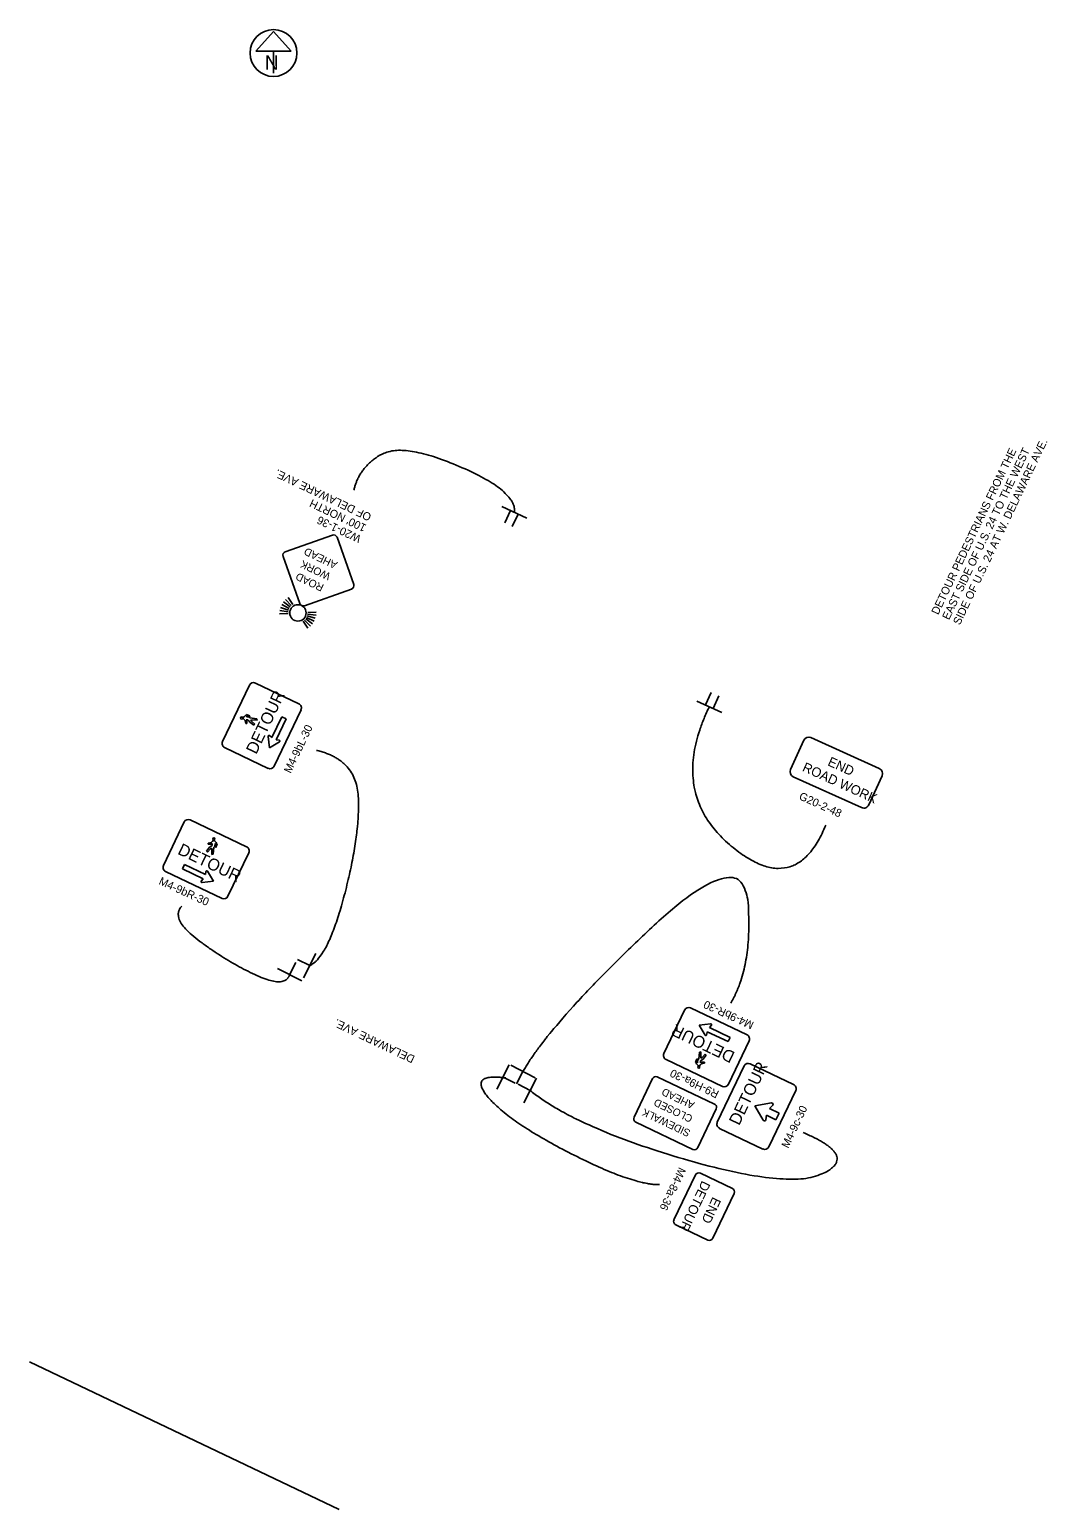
# Model space of a CAD drawing. Extents: x 186402 to 186758, y 352964 to 353482.
import ezdxf

# ---------------------------------------------------------------- set-up
doc = ezdxf.new("R2010")
doc.units = 0
for name, color, linetype in [('SH_Data', 7, 'Continuous'), ('SH_Masking', 7, 'Continuous'), ('SH_Text', 7, 'Continuous'), ('SN_P_Text', 7, 'Continuous')]:
    doc.layers.add(name, color=color, linetype=linetype)

msp = doc.modelspace()

# ---------------------------------------------------------------- linework, layer by layer
at = {"layer": 'SH_Data'}
msp.add_line((186510.16, 352964.46), (186401.84, 353016.1), dxfattribs=at)
msp.add_circle((186487.18, 353473.94), 8.2, dxfattribs=at)
at = {"layer": 'SH_Masking'}
for p, q in [((186487.18, 353481.42), (186481.03, 353474.59)), ((186493.33, 353474.59), (186487.18, 353481.42)), ((186481.03, 353474.59), (186493.33, 353474.59)), ((186487.18, 353474.59), (186487.18, 353466.86)), ((186567.13, 353315.32), (186575.79, 353311.19)), ((186570.16, 353313.88), (186568.1, 353309.54)), ((186571.46, 353313.26), (186571.46, 353313.26)), ((186572.76, 353312.64), (186570.7, 353308.3)), ((186493.02, 353280.18), (186490.68, 353281.97)), ((186493.43, 353280.63), (186491.45, 353282.78)), ((186493.91, 353280.99), (186492.31, 353283.49)), ((186492.31, 353277.9), (186489.32, 353277.76)), ((186492.33, 353278.51), (186489.39, 353278.89)), ((186492.45, 353279.1), (186489.66, 353279.98)), ((186492.69, 353279.67), (186490.07, 353281.02)), ((186501.81, 353276.19), (186499, 353277.05)), ((186502.07, 353277.26), (186499.13, 353277.64)), ((186502.14, 353278.36), (186499.16, 353278.24)), ((186499.23, 353272.7), (186497.6, 353275.22)), ((186500.1, 353273.39), (186498.09, 353275.59)), ((186500.8, 353274.25), (186498.48, 353276.03)), ((186501.37, 353275.19), (186498.77, 353276.53)), ((186477.3, 353240.43), (186477.52, 353239.34)), ((186477.59, 353240.7), (186478.26, 353240.71)), ((186477.84, 353240.36), (186477.59, 353240.7)), ((186477.6, 353241.82), (186477.75, 353242.11)), ((186478.97, 353242.02), (186477.73, 353242.5)), ((186477.73, 353242.5), (186477.73, 353242.49)), ((186477.75, 353242.11), (186478.83, 353241.77)), ((186478.26, 353240.71), (186478.54, 353240.34)), ((186478.83, 353241.77), (186478.97, 353242.02)), ((186478.91, 353241.36), (186478.89, 353241.42)), ((186481.33, 353241.07), (186478.91, 353241.36)), ((186479.48, 353240.21), (186479.25, 353240.66)), ((186479.25, 353240.66), (186481.43, 353240.59)), ((186481.43, 353240.59), (186481.33, 353241.07)), ((186490.11, 353241.74), (186486.63, 353234.45)), ((186488.13, 353233.73), (186491.61, 353241.02)), ((186491.61, 353241.02), (186490.11, 353241.74)), ((186477.52, 353239.34), (186477.83, 353239.39)), ((186477.83, 353239.39), (186477.84, 353240.36)), ((186478.54, 353240.34), (186478.94, 353239.85)), ((186478.94, 353239.85), (186480.29, 353238.8)), ((186480.69, 353239.11), (186479.48, 353240.21)), ((186480.29, 353238.8), (186480.69, 353239.11)), ((186485.33, 353234.89), (186485.84, 353230.85)), ((186485.84, 353230.85), (186489.29, 353233)), ((186486.63, 353234.45), (186485.85, 353235.16)), ((186489.17, 353233.58), (186488.13, 353233.73)), ((186464.84, 353196.09), (186463.79, 353194.74)), ((186463.79, 353194.74), (186464.1, 353194.34)), ((186464.1, 353194.34), (186465.19, 353195.56)), ((186465.42, 353197.73), (186464.33, 353197.51)), ((186464.33, 353197.51), (186464.38, 353197.2)), ((186464.38, 353197.2), (186465.35, 353197.19)), ((186465.33, 353196.5), (186464.84, 353196.09)), ((186465.19, 353195.56), (186465.65, 353195.78)), ((186465.69, 353196.77), (186465.33, 353196.5)), ((186465.35, 353197.19), (186465.68, 353197.44)), ((186465.65, 353195.78), (186465.58, 353193.6)), ((186465.68, 353197.44), (186465.69, 353196.77)), ((186466.06, 353193.7), (186466.35, 353196.12)), ((186466.35, 353196.12), (186466.41, 353196.15)), ((186467.1, 353197.29), (186466.76, 353196.2)), ((186466.76, 353196.2), (186467.01, 353196.06)), ((186466.81, 353197.44), (186467.1, 353197.29)), ((186467.01, 353196.06), (186467.49, 353197.3)), ((186467.49, 353197.3), (186467.48, 353197.3)), ((186455.34, 353188.51), (186456.05, 353190.02)), ((186456.05, 353190.02), (186463.35, 353186.54)), ((186465.58, 353193.6), (186466.06, 353193.7)), ((186462.63, 353185.04), (186455.34, 353188.51)), ((186461.92, 353184.26), (186462.63, 353185.04)), ((186466.23, 353184.24), (186462.19, 353183.74)), ((186463.35, 353186.54), (186463.5, 353187.58)), ((186464.08, 353187.7), (186466.23, 353184.24)), ((186502.06, 353158.97), (186497.68, 353150.43)), ((186497.08, 353149.32), (186488.55, 353153.71)), ((186492.81, 353151.51), (186495.01, 353155.78)), ((186499.87, 353154.7), (186495.6, 353156.89)), ((186636.11, 353133.87), (186640.15, 353134.37)), ((186638.26, 353130.42), (186636.11, 353133.87)), ((186640.42, 353133.85), (186639.71, 353133.08)), ((186639.71, 353133.08), (186647, 353129.6)), ((186638.99, 353131.57), (186638.84, 353130.54)), ((186646.29, 353128.1), (186638.99, 353131.57)), ((186647, 353129.6), (186646.29, 353128.1)), ((186635.33, 353122.05), (186634.85, 353120.82)), ((186635.24, 353120.83), (186635.58, 353121.91)), ((186635.58, 353121.91), (186635.33, 353122.05)), ((186635.99, 353121.99), (186635.93, 353121.97)), ((186636.28, 353124.41), (186635.99, 353121.99)), ((186636.76, 353124.51), (186636.28, 353124.41)), ((186636.64, 353121.34), (186637.01, 353121.62)), ((186636.65, 353120.67), (186636.64, 353121.34)), ((186636.69, 353122.33), (186636.76, 353124.51)), ((186637.15, 353122.56), (186636.69, 353122.33)), ((186637.01, 353121.62), (186637.5, 353122.02)), ((186638.24, 353123.77), (186637.15, 353122.56)), ((186637.5, 353122.02), (186638.55, 353123.37)), ((186638.55, 353123.37), (186638.24, 353123.77)), ((186565.33, 353111.44), (186569.72, 353119.98)), ((186570.2, 353119.82), (186578.74, 353115.44)), ((186574.47, 353117.63), (186572.28, 353113.36)), ((186634.85, 353120.82), (186634.86, 353120.81)), ((186635.53, 353120.68), (186635.24, 353120.83)), ((186636.99, 353120.92), (186636.65, 353120.67)), ((186636.92, 353120.38), (186638.01, 353120.6)), ((186637.96, 353120.91), (186636.99, 353120.92)), ((186638.01, 353120.6), (186637.96, 353120.91)), ((186567.53, 353115.71), (186571.8, 353113.52)), ((186577.02, 353111.01), (186572.76, 353113.21)), ((186579.22, 353115.28), (186574.83, 353106.74)), ((186619.83, 353115.21), (186613.37, 353101.66)), ((186641.51, 353106.23), (186621.41, 353115.82)), ((186661.43, 353106.67), (186655.68, 353105.7)), ((186660.77, 353104.67), (186661.88, 353105.85)), ((186635.67, 353091.02), (186642.11, 353104.54)), ((186655.68, 353105.7), (186658.55, 353100.61)), ((186659.46, 353100.79), (186659.68, 353102.39)), ((186659.68, 353102.39), (186659.7, 353102.38)), ((186659.7, 353102.38), (186663.03, 353100.79)), ((186663.03, 353100.79), (186664.12, 353103.08)), ((186613.97, 353099.96), (186633.97, 353090.42))]:
    msp.add_line(p, q, dxfattribs=at)
for points in [[(186491.32, 353299.44), (186507.82, 353305.29)], [(186509.42, 353304.53), (186515.26, 353288.03)], [(186496.41, 353281.35), (186490.56, 353297.85)], [(186514.5, 353286.44), (186498, 353280.59)], [(186478.76, 353252.8), (186469.35, 353233.06)], [(186496.08, 353246.28), (186480.84, 353253.54)], [(186487.4, 353224.45), (186496.82, 353244.2)], [(186470.09, 353230.98), (186485.32, 353223.71)], [(186455.96, 353204.95), (186448.7, 353189.71)], [(186477.79, 353196.27), (186458.05, 353205.68)], [(186471.27, 353178.96), (186478.53, 353194.19)], [(186449.44, 353187.63), (186469.19, 353178.22)], [(186631.07, 353139.16), (186623.81, 353123.93)], [(186652.9, 353130.48), (186633.15, 353139.9)], [(186646.38, 353113.17), (186653.64, 353128.4)], [(186624.55, 353121.84), (186644.29, 353112.43)], [(186651.88, 353119.58), (186642.5, 353099.9)], [(186669.18, 353113.11), (186654.02, 353120.34)], [(186660.55, 353091.3), (186669.94, 353110.98)], [(186664.12, 353103.08), (186660.79, 353104.66)], [(186643.26, 353097.77), (186658.42, 353090.54)], [(186634.83, 353081.48), (186627.34, 353065.77)], [(186647.76, 353076.75), (186636.57, 353082.09)], [(186640.88, 353059.32), (186648.37, 353075.02)], [(186627.96, 353064.04), (186639.15, 353058.7)]]:
    msp.add_lwpolyline(points, dxfattribs=at)
for centre, radius in [((186487.18, 353473.94), 8.2), ((186495.73, 353278.09), 2.87), ((186476.07, 353241.31), 0.383), ((186466.3, 353198.97), 0.383), ((186636.04, 353119.15), 0.383)]:
    msp.add_circle(centre, radius, dxfattribs=at)
for centre, radius, start, end in [((186508.24, 353304.11), 1.25, 19.5098, 109.5098), ((186491.74, 353298.27), 1.25, 109.5098, 199.5098), ((186514.08, 353287.61), 1.25, 289.5098, 19.5098), ((186497.59, 353281.77), 1.25, 199.5098, 289.5098), ((186480.17, 353252.13), 1.56, 64.5098, 154.5098), ((186495.4, 353244.87), 1.56, 334.5098, 64.5098), ((186485.64, 353234.93), 0.313, 47.5578, 187.1083), ((186470.76, 353232.39), 1.56, 154.5098, 244.5098), ((186489.12, 353233.27), 0.313, 301.9112, 81.4617), ((186485.99, 353225.12), 1.56, 244.5098, 334.5098), ((186457.37, 353204.27), 1.56, 64.5098, 154.5098), ((186477.12, 353194.86), 1.56, 334.5098, 64.5098), ((186450.11, 353189.04), 1.56, 154.5098, 244.5098), ((186462.15, 353184.05), 0.313, 137.5578, 277.1083), ((186463.81, 353187.53), 0.313, 31.9112, 171.4617), ((186469.86, 353179.63), 1.56, 244.5098, 334.5098), ((186632.48, 353138.49), 1.56, 64.5098, 154.5098), ((186640.19, 353134.06), 0.312, 317.5578, 97.1083), ((186638.53, 353130.58), 0.312, 211.9112, 351.4617), ((186652.23, 353129.07), 1.56, 334.5098, 64.5098), ((186625.22, 353123.25), 1.56, 154.5098, 244.5098), ((186653.33, 353118.89), 1.6, 64.5098, 154.5098), ((186620.96, 353114.63), 1.27, 64.5098, 154.5098), ((186644.96, 353113.84), 1.56, 244.5098, 334.5098), ((186668.49, 353111.66), 1.6, 334.5098, 64.5098), ((186640.97, 353105.09), 1.27, 334.5098, 64.5098), ((186661.52, 353106.19), 0.493, 316.872, 99.589), ((186614.52, 353101.11), 1.27, 154.5098, 244.5098), ((186658.98, 353100.85), 0.493, 209.4305, 352.1476), ((186643.95, 353099.22), 1.6, 154.5098, 244.5098), ((186634.52, 353091.57), 1.27, 244.5098, 334.5098), ((186659.11, 353091.99), 1.6, 244.5098, 334.5098), ((186636.01, 353080.92), 1.3, 64.5098, 154.5098), ((186647.2, 353075.58), 1.3, 334.5098, 64.5098), ((186628.52, 353065.21), 1.3, 154.5098, 244.5098), ((186639.71, 353059.88), 1.3, 244.5098, 334.5098)]:
    msp.add_arc(centre, radius, start, end, dxfattribs=at)
for points, degree in [([(186571.46, 353313.26), (186572.64, 353320.51), (186532.28, 353337.95), (186516.98, 353328.76), (186515.31, 353320.97)], 2), ([(186477.73, 353242.49), (186477.41, 353242.21), (186476.89, 353241.78), (186476.7, 353241.62), (186476.65, 353241.56), (186476.62, 353241.49), (186476.55, 353241.33), (186476.64, 353241.04), (186476.89, 353240.78), (186477.06, 353240.58), (186477.3, 353240.43)], 3), ([(186478.89, 353241.42), (186478.84, 353241.49), (186478.76, 353241.58), (186478.55, 353241.66), (186478.37, 353241.7), (186478.04, 353241.76), (186477.81, 353241.8), (186477.6, 353241.82)], 3), ([(186499.87, 353154.7), (186506.11, 353157.37), (186517.41, 353199.58), (186516.41, 353226.78), (186502.19, 353230)], 2), ([(186467.48, 353197.3), (186467.2, 353197.62), (186466.77, 353198.14), (186466.61, 353198.33), (186466.55, 353198.38), (186466.48, 353198.41), (186466.32, 353198.49), (186466.02, 353198.39), (186465.77, 353198.14), (186465.57, 353197.97), (186465.42, 353197.73)], 3), ([(186466.41, 353196.15), (186466.48, 353196.19), (186466.57, 353196.27), (186466.65, 353196.48), (186466.69, 353196.66), (186466.75, 353196.99), (186466.79, 353197.22), (186466.81, 353197.44)], 3), ([(186647.19, 353141.6), (186654.8, 353154.34), (186651.77, 353198.57), (186584.16, 353134.54), (186574.47, 353117.63)], 2), ([(186492.81, 353151.51), (186491.35, 353146.54), (186470.25, 353156.44), (186450.96, 353171.17), (186455.12, 353175.53)], 2), ([(186635.93, 353121.97), (186635.86, 353121.92), (186635.77, 353121.84), (186635.69, 353121.63), (186635.65, 353121.45), (186635.59, 353121.13), (186635.55, 353120.9), (186635.53, 353120.68)], 3), ([(186634.86, 353120.81), (186635.14, 353120.49), (186635.57, 353119.97), (186635.73, 353119.78), (186635.79, 353119.73), (186635.86, 353119.7), (186636.02, 353119.63), (186636.31, 353119.72), (186636.57, 353119.97), (186636.77, 353120.14), (186636.92, 353120.38)], 3), ([(186568.49, 353115.4), (186555.07, 353117.17), (186569.7, 353099.93), (186613.01, 353077.87), (186622.31, 353078.08)], 2), ([(186577.02, 353111.01), (186592.96, 353098.08), (186668.25, 353076.07), (186691.7, 353088.25), (186672.58, 353096.26)], 2)]:
    msp.add_open_spline(points, degree=degree, dxfattribs=at)
at = {"layer": 'SH_Text'}
for p, q in [((186644.09, 353243.3), (186635.34, 353247.26)), ((186638.4, 353245.87), (186640.39, 353250.24)), ((186641.03, 353244.68), (186643.01, 353249.06)), ((186639.72, 353245.28), (186639.72, 353245.28)), ((186639.72, 353245.28), (186639.72, 353245.28))]:
    msp.add_line(p, q, dxfattribs=at)
for points in [[(186672.8, 353233.52), (186668.16, 353223.28)], [(186699.19, 353223.62), (186675.28, 353234.46)], [(186669.09, 353220.79), (186693, 353209.96)], [(186695.48, 353210.89), (186700.13, 353221.14)]]:
    msp.add_lwpolyline(points, dxfattribs=at)
for centre, radius, start, end in [((186674.51, 353232.75), 1.87, 65.6179, 155.6179), ((186669.87, 353222.5), 1.88, 155.6179, 245.6179), ((186698.42, 353221.91), 1.88, 335.6179, 65.6179), ((186693.78, 353211.67), 1.87, 245.6179, 335.6179)]:
    msp.add_arc(centre, radius, start, end, dxfattribs=at)
at = {"layer": 'SN_P_Text'}
msp.add_open_spline([(186680.44, 353203.82), (186669.75, 353177.82), (186625.03, 353215.2), (186639.72, 353245.28)], degree=2, dxfattribs=at)

# ---------------------------------------------------------------- texts
at = {"layer": 'SH_Masking'}
msp.add_text('N', height=5, dxfattribs=at).set_placement((186484.16, 353468.12))
for s, height, rotation, p in [('DETOUR PEDESTRIANS FROM THE', 2.8, 64.5098, (186719.78, 353277.22)), ('EAST SIDE OF U.S. 24 TO THE WEST ', 2.8, 64.5098, (186723.57, 353275.42)), ('SIDE OF U.S. 24 AT W. DELAWARE AVE.', 2.8, 64.5098, (186727.36, 353273.61)), ('OF DELAWARE AVE.', 2.8, 154.5098, (186521.73, 353312.57)), ("100' NORTH", 2.8, 154.5098, (186519.93, 353308.78)), ('W20-1-36', 2.8, 154.5098, (186518.12, 353304.99)), ('AHEAD', 2.665, 154.5098, (186509.78, 353295.76)), ('WORK', 2.665, 154.5098, (186507.42, 353291.81)), ('ROAD', 2.665, 154.5098, (186505.05, 353287.86)), ('DETOUR', 4.167, 64.5098, (186481.15, 353228.38)), ('M4-9bL-30', 2.8, 64.5098, (186493.2, 353221.75)), ('DETOUR', 4.167, 334.5098, (186453.37, 353193.88)), ('M4-9bR-30', 2.8, 335.4956, (186446.8, 353183.26)), ('M4-9bR-30', 2.8, 155.4956, (186655.53, 353134.85)), ('DELAWARE AVE.', 2.8, 154.5098, (186536.89, 353122.97)), ('DETOUR', 4.167, 154.5098, (186648.97, 353124.23)), ('R9-H9a-30', 2.8, 154.5098, (186643.35, 353110.71)), ('DETOUR', 4.167, 64.5098, (186650.15, 353098.53)), ('AHEAD', 2.627, 154.5098, (186634.78, 353106.76)), ('CLOSED', 2.627, 154.5098, (186634.14, 353102.05)), ('SIDEWALK', 2.627, 154.5098, (186633.35, 353097.03)), ('M4-9c-30', 2.8, 64.5098, (186667.31, 353090.6)), ('M4-8a-36', 2.8, 244.5098, (186629.12, 353084.37)), ('DETOUR', 3.333, 244.5098, (186637.2, 353079.68)), ('END', 3.333, 244.5098, (186640.93, 353073.99))]:
    msp.add_text(s, height=height, rotation=rotation, dxfattribs=at).set_placement(p)
at = {"layer": 'SH_Text'}
for s, p in [('ROAD WORK', (186671.99, 353222.91)), ('END', (186680.85, 353224.84))]:
    msp.add_text(s, height=3.333, rotation=335.6179, dxfattribs=at).set_placement(p)
at = {"layer": 'SN_P_Text'}
msp.add_text('G20-2-48', height=2.8, rotation=335.6179, dxfattribs=at).set_placement((186670.83, 353212.98))

doc.saveas('drawing.dxf')
